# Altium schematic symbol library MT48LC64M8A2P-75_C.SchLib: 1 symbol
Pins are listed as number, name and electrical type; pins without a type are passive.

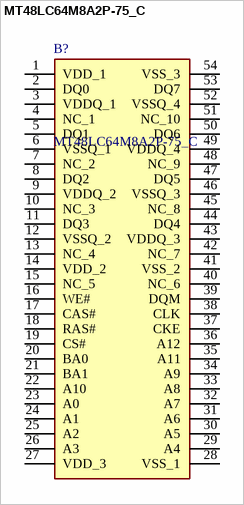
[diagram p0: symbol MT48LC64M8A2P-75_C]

## MT48LC64M8A2P-75_C
designator B?
DRAM 512Mb, 3.3v, 133Mhz 64M x 8 SDR; Manufacturer_Name: Alliance Memory; Manufacturer_Part_Number: MT48LC64M8A2P-75:C; Geometry.Height: 1.2mm
footprint SOP80P1176X120-54N
pins: 1 VDD_1, 2 DQ0, 3 VDDQ_1, 4 NC_1, 5 DQ1, 6 VSSQ_1, 7 NC_2, 8 DQ2, 9 VDDQ_2, 10 NC_3, 11 DQ3, 12 VSSQ_2, 13 NC_4, 14 VDD_2, 15 NC_5, 16 WE#, 17 CAS#, 18 RAS#, 19 CS#, 20 BA0, 21 BA1, 22 A10, 23 A0, 24 A1, 25 A2, 26 A3, 27 VDD_3, 28 VSS_1, 29 A4, 30 A5, 31 A6, 32 A7, 33 A8, 34 A9, 35 A11, 36 A12, 37 CKE, 38 CLK, 39 DQM, 40 NC_6, 41 VSS_2, 42 NC_7, 43 VDDQ_3, 44 DQ4, 45 NC_8, 46 VSSQ_3, 47 DQ5, 48 NC_9, 49 VDDQ_4, 50 DQ6, 51 NC_10, 52 VSSQ_4, 53 DQ7, 54 VSS_3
